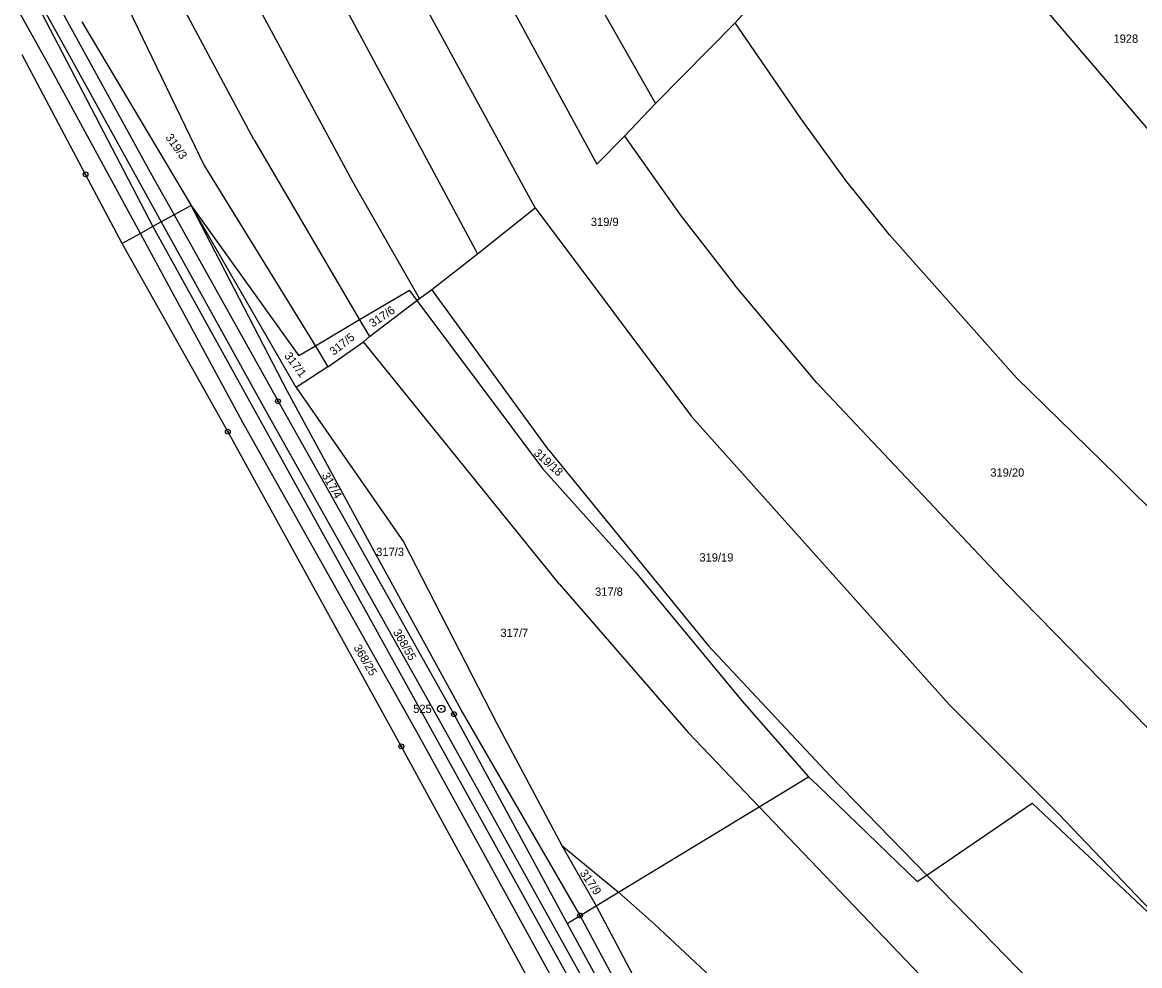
# Model space of a CAD drawing. Extents: x -762263 to -760336, y -1154405 to -1152076.
# Drawn here: x -761293.1 to -761064.3, y -1153317.8 to -1153124.6 of the extents above; entities that cross this region are included whole.
import ezdxf

# ---------------------------------------------------------------- set-up
doc = ezdxf.new("R2010")
doc.units = 0
for name, color, linetype in [('Vrstva 1', 7, 'Continuous'), ('Vrstva 17', 7, 'Continuous'), ('Vrstva 18', 7, 'Continuous'), ('Vrstva 24', 7, 'Continuous'), ('Vrstva 4', 7, 'Continuous'), ('Vrstva 6', 7, 'Continuous')]:
    doc.layers.add(name, color=color, linetype=linetype)

msp = doc.modelspace()

# ---------------------------------------------------------------- linework, layer by layer
at = {"layer": 'Vrstva 1'}
for p, q in [((-761302.14, -1153097.65), (-761266.33, -1153166.38)), ((-761291.65, -1153110.16), (-761266.13, -1153156.64)), ((-761280.9, -1153124.46), (-761258.5, -1153162.06)), ((-761280.13, -1153155.69), (-761293.15, -1153131.24)), ((-761272.63, -1153169.86), (-761280.13, -1153155.69)), ((-761266.13, -1153156.64), (-761262.02, -1153164)), ((-761258.5, -1153162.06), (-761262.02, -1153164)), ((-761258.5, -1153162.06), (-761236.44, -1153192.88)), ((-761262.02, -1153164), (-761264.63, -1153165.44)), ((-761262.02, -1153164), (-761240.73, -1153202.17)), ((-761266.33, -1153166.38), (-761268.92, -1153167.81)), ((-761264.63, -1153165.44), (-761266.33, -1153166.38)), ((-761266.33, -1153166.38), (-761146.19, -1153383.6)), ((-761268.92, -1153167.81), (-761272.63, -1153169.86)), ((-761251.01, -1153208.39), (-761272.63, -1153169.86)), ((-761213.81, -1153179.46), (-761224.01, -1153185.51)), ((-761213.81, -1153179.46), (-761212.27, -1153181.52)), ((-761212.27, -1153181.52), (-761186.56, -1153215.97)), ((-761224.01, -1153185.51), (-761233.04, -1153190.87)), ((-761233.04, -1153190.87), (-761236.44, -1153192.88)), ((-761240.73, -1153202.17), (-761204.69, -1153266.27)), ((-761215.48, -1153272.86), (-761251.01, -1153208.39)), ((-761186.56, -1153215.97), (-761167.6, -1153237.13)), ((-761167.6, -1153237.13), (-761145.71, -1153263.59)), ((-761145.71, -1153263.59), (-761132.09, -1153279.08)), ((-761204.69, -1153266.27), (-761181.49, -1153309.12)), ((-761181.37, -1153335.36), (-761215.48, -1153272.86)), ((-761142.21, -1153285.24), (-761132.09, -1153279.08)), ((-761132.09, -1153279.08), (-761130.17, -1153280.88)), ((-761109.81, -1153300.56), (-761130.17, -1153280.88)), ((-761170.97, -1153302.73), (-761142.21, -1153285.24)), ((-761107.84, -1153299.22), (-761086.26, -1153284.52)), ((-761086.26, -1153284.52), (-761052.85, -1153316.07)), ((-761109.81, -1153300.56), (-761107.84, -1153299.22)), ((-761175.56, -1153305.52), (-761170.97, -1153302.73)), ((-761178.87, -1153307.53), (-761175.56, -1153305.52)), ((-761181.49, -1153309.12), (-761178.87, -1153307.53)), ((-761168.04, -1153327.74), (-761178.87, -1153307.53)), ((-761181.49, -1153309.12), (-761170.44, -1153329.52))]:
    msp.add_line(p, q, dxfattribs=at)
at = {"layer": 'Vrstva 24'}
for centre, radius in [((-761280.13, -1153155.69), 0.5), ((-761280.13, -1153155.69), 0.1), ((-761240.73, -1153202.17), 0.5), ((-761240.73, -1153202.17), 0.1), ((-761251.01, -1153208.39), 0.5), ((-761251.01, -1153208.39), 0.1), ((-761207.29, -1153265.18), 0.75), ((-761207.29, -1153265.18), 0.1), ((-761204.69, -1153266.27), 0.5), ((-761204.69, -1153266.27), 0.1), ((-761215.48, -1153272.86), 0.5), ((-761215.48, -1153272.86), 0.1), ((-761178.87, -1153307.53), 0.5), ((-761178.87, -1153307.53), 0.1)]:
    msp.add_circle(centre, radius, dxfattribs=at)
at = {"layer": 'Vrstva 4'}
for p, q in [((-761287.38, -1153133.79), (-761313.24, -1153087.23)), ((-761302.14, -1153097.65), (-761283.45, -1153131.38)), ((-761283.45, -1153131.38), (-761264.63, -1153165.44)), ((-761268.92, -1153167.81), (-761287.38, -1153133.79)), ((-761264.63, -1153165.44), (-761243.44, -1153203.81)), ((-761247.92, -1153206.52), (-761268.92, -1153167.81)), ((-761243.44, -1153203.81), (-761207.48, -1153267.98)), ((-761211.89, -1153270.67), (-761247.92, -1153206.52)), ((-761207.48, -1153267.98), (-761172.64, -1153330.69)), ((-761177.43, -1153333.26), (-761211.89, -1153270.67))]:
    msp.add_line(p, q, dxfattribs=at)
at = {"layer": 'Vrstva 6'}
for p, q in [((-761185.67, -1153101.92), (-761163.42, -1153141.18)), ((-761245.65, -1153148.53), (-761268.21, -1153106.39)), ((-761234.72, -1153106.98), (-761199.88, -1153172)), ((-761188.09, -1153162.54), (-761218.52, -1153106.64)), ((-761147.11, -1153124.64), (-761137.58, -1153114.14)), ((-761194.67, -1153118.18), (-761175.45, -1153153.62)), ((-761272.4, -1153119.63), (-761255.86, -1153153.87)), ((-761225.4, -1153157.19), (-761245.74, -1153119.44)), ((-761048.79, -1153162.61), (-761084.16, -1153121.16)), ((-761163.42, -1153141.18), (-761147.11, -1153124.64)), ((-761133.77, -1153144.02), (-761147.11, -1153124.64)), ((-761169.78, -1153147.86), (-761163.42, -1153141.18)), ((-761124.48, -1153156.92), (-761133.77, -1153144.02)), ((-761175.45, -1153153.62), (-761169.78, -1153147.86)), ((-761169.78, -1153147.86), (-761158.4, -1153164.01)), ((-761245.65, -1153148.53), (-761224.01, -1153185.51)), ((-761255.86, -1153153.87), (-761233.04, -1153190.87)), ((-761211.74, -1153181.12), (-761225.4, -1153157.19)), ((-761115.49, -1153168.11), (-761124.48, -1153156.92)), ((-761238.77, -1153200.2), (-761258.5, -1153162.06)), ((-761236.99, -1153199.38), (-761258.5, -1153162.06)), ((-761199.88, -1153172), (-761188.09, -1153162.54)), ((-761188.09, -1153162.54), (-761156.03, -1153205.29)), ((-761158.4, -1153164.01), (-761147.23, -1153178.29)), ((-761089.47, -1153197.4), (-761115.49, -1153168.11)), ((-761209.21, -1153179.25), (-761199.88, -1153172)), ((-761211.74, -1153181.12), (-761209.21, -1153179.25)), ((-761185.28, -1153212.16), (-761209.21, -1153179.25)), ((-761130.42, -1153198.37), (-761147.23, -1153178.29)), ((-761222.02, -1153188.91), (-761212.27, -1153181.52)), ((-761212.27, -1153181.52), (-761211.74, -1153181.12)), ((-761224.01, -1153185.51), (-761222.02, -1153188.91)), ((-761223.2, -1153189.98), (-761222.02, -1153188.91)), ((-761233.04, -1153190.87), (-761230.52, -1153195.09)), ((-761230.52, -1153195.09), (-761223.2, -1153189.98)), ((-761183.12, -1153239.57), (-761223.2, -1153189.98)), ((-761230.52, -1153195.09), (-761236.99, -1153199.38)), ((-761091.45, -1153239.65), (-761130.42, -1153198.37)), ((-761069.11, -1153217.28), (-761089.47, -1153197.4)), ((-761220.6, -1153233.66), (-761238.77, -1153200.2)), ((-761236.99, -1153199.38), (-761215.02, -1153230.99)), ((-761156.03, -1153205.29), (-761103.26, -1153264.32)), ((-761185.28, -1153212.16), (-761152.62, -1153252.22)), ((-761040.25, -1153246.08), (-761069.11, -1153217.28)), ((-761215.02, -1153230.99), (-761196.01, -1153268.05)), ((-761203.21, -1153265.41), (-761220.6, -1153233.66)), ((-761183.12, -1153239.57), (-761156.77, -1153270.04)), ((-761059.24, -1153272.57), (-761091.45, -1153239.65)), ((-761127.67, -1153278.88), (-761152.62, -1153252.22)), ((-761103.26, -1153264.32), (-761080.89, -1153286.7)), ((-761178.87, -1153307.53), (-761203.21, -1153265.41)), ((-761196.01, -1153268.05), (-761182.58, -1153293.18)), ((-761156.77, -1153270.04), (-761142.21, -1153285.24)), ((-761127.67, -1153278.88), (-761107.84, -1153299.22)), ((-761142.21, -1153285.24), (-761105.65, -1153323.41)), ((-761052.85, -1153316.07), (-761080.89, -1153286.7)), ((-761182.58, -1153293.18), (-761170.97, -1153302.73)), ((-761182.58, -1153293.18), (-761175.56, -1153305.52)), ((-761107.84, -1153299.22), (-761096.46, -1153310.9)), ((-761170.97, -1153302.73), (-761163.61, -1153309.3)), ((-761175.56, -1153305.52), (-761156.64, -1153341.17)), ((-761163.61, -1153309.3), (-761131.94, -1153338.85)), ((-761072, -1153336.15), (-761096.46, -1153310.9))]:
    msp.add_line(p, q, dxfattribs=at)

# ---------------------------------------------------------------- texts
at = {"layer": 'Vrstva 17'}
msp.add_text('525', height=1.7, dxfattribs=at).set_placement((-761213.044, -1153266.03))
at = {"layer": 'Vrstva 18'}
for s, p in [('1928', (-761069.639, -1153128.74)), ('319/9', (-761176.662, -1153166.27)), ('319/20', (-761094.862, -1153217.62)), ('317/3', (-761220.619, -1153233.88)), ('319/19', (-761154.433, -1153235.01)), ('317/8', (-761175.802, -1153242.02)), ('317/7', (-761195.182, -1153250.46))]:
    msp.add_text(s, height=1.7, dxfattribs=at).set_placement(p)
for s, rotation, p in [('319/3', 305.04273, (-761263.851, -1153148.122)), ('317/6', 33.9191, (-761221.329, -1153187.098)), ('317/5', 38.15899, (-761229.33, -1153192.874)), ('317/1', 306.87619, (-761239.531, -1153192.893)), ('319/18', 317.87699, (-761188.481, -1153213.01)), ('317/4', 300.0007, (-761231.826, -1153217.368)), ('368/55', 300.0007, (-761217.241, -1153249.456)), ('368/25', 300.28718, (-761225.32, -1153252.615)), ('317/9', 304.64166, (-761179.01, -1153298.833))]:
    msp.add_text(s, height=1.7, rotation=rotation, dxfattribs=at).set_placement(p)

doc.saveas('drawing.dxf')
